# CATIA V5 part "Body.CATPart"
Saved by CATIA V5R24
Part number: Body
Bounding box of the stored display mesh (mm): x -15.965 to 16, y -19 to 19, z 0 to 5.5
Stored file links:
  C:\Users\Jules\Documents\ECL\Watch\Body.CATPart
  C:\Users\Jules\Documents\ECL\Watch\Clip.CATPart
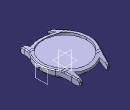
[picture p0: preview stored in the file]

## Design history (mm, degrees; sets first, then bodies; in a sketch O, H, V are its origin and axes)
Body1 (main body)
  Sketch1 on xy-plane, origin (0, 0, 0), H (1, 0, 0), V (0, 1, 0)
    arc A1 centre (0, 0) radius 16 from (-13.9491, 7.8372) to (-13.9491, -7.8372) ccw
    point P1 (-8, 13.8564)
    line L1 (-8, 13.8564) -> (-8, 19)
    point P2 (-8, 19)
    line L2 (-8, 19) -> (-9.5, 19)
    point P3 (-9.5, 19)
    line L3 (-9.5, 19) -> (-10.7872, 15.0465)
    point P4 (-12.3901, 10.1236)
    arc A2 centre (-48.822, 27.4301) radius 40 from (-13.9491, 7.8372) to (-10.7872, 15.0465) ccw
    point P5 (-13.9491, 7.8372)
    point P6 (-10.7872, 15.0465)
    point P7 (-8, 13.8564)
    point P9 (10.7872, 15.0465)
    point P10 (13.9491, 7.8372)
    arc A3 centre (48.822, 27.4301) radius 40 from (13.9491, 7.8372) to (10.7872, 15.0465) cw
    point P12 (9.5, 19)
    line L4 (9.5, 19) -> (10.7872, 15.0465)
    point P13 (8, 19)
    line L5 (8, 19) -> (9.5, 19)
    point P14 (8, 13.8564)
    line L6 (8, 13.8564) -> (8, 19)
    point P15 (10.7872, -15.0465)
    point P16 (13.9491, -7.8372)
    arc A4 centre (48.822, -27.4301) radius 40 from (13.9491, -7.8372) to (10.7872, -15.0465) ccw
    point P18 (9.5, -19)
    point P19 (8, -19)
    line L7 (8, -19) -> (9.5, -19)
    line L8 (9.5, -19) -> (10.7872, -15.0465)
    point P20 (8, -13.8564)
    line L9 (8, -13.8564) -> (8, -19)
    point P21 (-8, -19)
    point P22 (-8, -13.8564)
    line L10 (-8, -13.8564) -> (-8, -19)
    point P23 (-9.5, -19)
    line L11 (-8, -19) -> (-9.5, -19)
    point P24 (-10.7872, -15.0465)
    line L12 (-9.5, -19) -> (-10.7872, -15.0465)
    point P25 (-13.9491, -7.8372)
    arc A5 centre (-48.822, -27.4301) radius 40 from (-13.9491, -7.8372) to (-10.7872, -15.0465) cw
    arc A6 centre (0, 0) radius 16 from (8, 13.8564) to (-8, 13.8564) ccw
    arc A7 centre (0, 0) radius 16 from (13.9491, -7.8372) to (13.9491, 7.8372) ccw
    arc A8 centre (0, 0) radius 16 from (-8, -13.8564) to (8, -13.8564) ccw
    radius A2 = 40
    radius A1 = 16
    distance L1 V = 8
    distance H P3 = 19
    length L2 = 1.5
    coincidence: P1 A1, P4 A1, L3 P4, P7 P1, A1 A6, A1 A7, A1 A8
    vertical: L1 V
    horizontal: L2 H
    tangency: A2 L3, A2 A1
    symmetry: P6 P9 V, P5 P10 V, A2 A3 V, P3 P12 V, L3 L4 V, P2 P13 V, L2 L5 V, P1 P14 V, L1 L6 V, P9 P15 H, P10 P16 H, A3 A4 H, P12 P18 H, P13 P19 H, L5 L7 H, L4 L8 H, P14 P20 H, L6 L9 H, P2 P21 H, P1 P22 H, L1 L10 H, P3 P23 H, L2 L11 H, P6 P24 H, L3 L12 H, P5 P25 H, A2 A5 H
  Pad1: profile Sketch1, direction (0, 0, 1), length 5.5
  Sketch2 on zx-plane, origin (0, 0, 0), H (-1, 0, 0), V (0, 0, 1)
    projected line E1 (-16, 0) -> (-16, 5.5) from face of Pad1 from Sketch1.A7
    point P3 (-16, 2.5)
    line L1 (-16, 2.5) -> (-19.5704, 0)
    point P4 (-19.5704, 0)
    line L2 (-19.5704, 0) -> (-13.5, 0)
    line L3 (-13.5, 0) -> (-16, 2.5)
    angle L1 L2 = 35
    angle L3 L2 = 45
    distance L2 P3 = 2.5
    coincidence: P3 E1, P4 H
    horizontal: L2 H
  Groove1: profile Sketch2, axis Sketch2.V, angle 360
  Sketch3 on yz-plane, origin (0, 0, 0), H (0, 1, 0), V (0, 0, 1)
    reference projected curve E1 from face of Pad1 from Sketch1.L8
    point P1 (-19, 3)
    line L1 (-19, 3) -> (0, 8.8089)
    point P2 (0, 8.8089)
    reference projected line E2 through (0, 0) direction (0, 1) from axis of face of Groove1 from Sketch2.L3
    point P5 (0, 8.8089)
    point P6 (19, 3)
    line L2 (19, 3) -> (0, 8.8089)
    distance P1 H = 3
    angle L1 H = 17
    coincidence: P1 E1, P2 V, P2 P5
    symmetry: P2 P5 E2, P1 P6 E2, L1 L2 E2
  Pocket1: profile Sketch3, direction (-1, 0, 0), through (limit type 3), opposite side through (limit type 3), thin wall 0, second thickness 5
  Sketch4 on end face of Pad1, origin (0, 0, 5.5), H (1, 0, 0), V (0, 1, 0)
    circle A1 centre (0, 0) radius 14
    radius A1 = 14
  Pocket2: profile Sketch4, direction (0, 0, -1), length 1.5
  Plane1: type Offset, RefPlane yz-plane, Offset 15
  Sketch5 on Plane1, origin (15, 0, 0), H (0, 1, 0), V (0, 0, 1)
    circle A1 centre (0, 2.5) radius 1.5
    point P1 (0, 2.5)
    radius A1 = 1.5
    distance P1 H = 2.5
    coincidence: P1 V
  Pocket3: profile Sketch5, direction (1, 0, 0), through (limit type 3)
  Fillet1: radius 2, on edge [face of Pocket1 | face of Pad1 from Sketch1.L7]; edge [face of Pocket1 | face of Pad1 from Sketch1.L11]; edge [face of Pad1 from Sketch1.L2 | face of Pocket1]; edge [face of Pad1 from Sketch1.L5 | face of Pocket1]
  Fillet2: radius 5, on edge [face of Pocket1 | end face of Pad1] (x2); edge [end face of Pad1 | face of Pocket1] (x2)
  Chamfer1: length 0.5, angle 45, on edge [face of Pad1 from Sketch1.A7 | end face of Pad1]; edge [face of Pad1 from Sketch1.A1 | end face of Pad1]
  Sketch6 on yz-plane, origin (0, 0, 0), H (0, 1, 0), V (0, 0, 1)
    construction line L1 (-21, 2.85) -> (-18, 2.85)
    construction arc A1 centre (-18, 1.4) radius 1.45 from (-18, 2.85) to (-16.5731, 1.658) cw
    point P3 (-18, 1.4)
    point P4 (-18.0483, -0.0492)
    point P5 (-21.0467, 0.0508)
    construction arc A2 centre (-21, 1.45) radius 1.4 from (-21.7039, 0.2398) to (-21, 2.85) cw
    circle A3 centre (-18, 1.4) radius 0.55
    construction circle A4 centre (-21, 1.45) radius 0.55
    construction line L2 (-16.5731, 1.658) -> (-16.021, -1.3948)
    construction line L3 (-16.021, -1.3948) -> (-21.7039, 0.2398)
    radius A1 = 1.45
    distance P3 V = 18
    radius A3 = 0.55
    radius A4 = 0.55
    distance P3 H = 1.4
    distance P4 P5 = 3
    horizontal: L1 H
    tangency: A1 L1, A2 L1, L2 A1
    coincidence: L3 P5
  Pocket4: profile Sketch6, direction (-1, 0, 0), length 8.7, mirrored extent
